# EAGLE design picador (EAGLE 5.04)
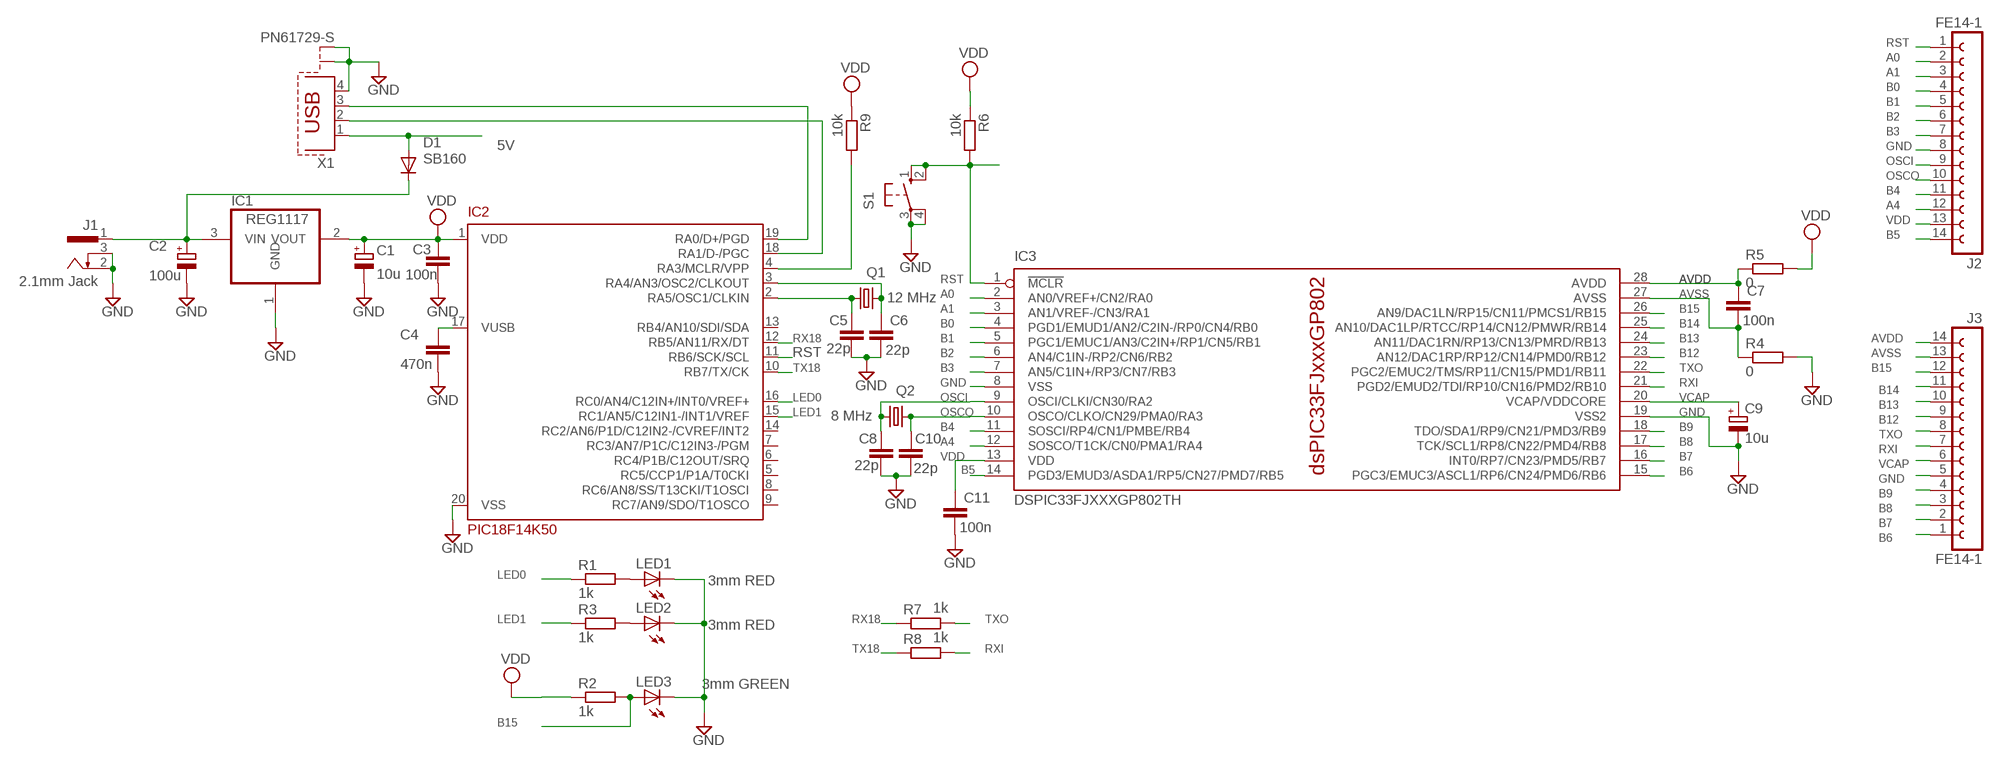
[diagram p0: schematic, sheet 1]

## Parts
C1  10u  CPOL-EUE2-4  [E2-4]
C2  100u  CPOL-EUE2-4  [E2-4]
C3  100n  C-EU025-024X044  [C025-024X044]
C4  470n  C-EU025-024X044  [C025-024X044]
C5  22p  C-EU025-024X044  [C025-024X044]
C6  22p  C-EU025-024X044  [C025-024X044]
C7  100n  C-EU025-024X044  [C025-024X044]
C8  22p  C-EU025-024X044  [C025-024X044]
C9  10u  CPOL-EUE2-4  [E2-4]
C10  22p  C-EU025-024X044  [C025-024X044]
C11  100n  C-EU025-024X044  [C025-024X044]
D1  SB160  SB120  [DO41-10]
IC1  REG1117  [SOT223]
IC2  PIC18F14K50  [DIL20]
IC3  DSPIC33FJXXXGP802TH  [DIL28-3]
J1  2.1mm Jack  733980-62  [733980-62]
J2  FE14-1  [FE13]
J3  FE14-1  [FE13]
LED1  3mm RED  LED3MM  [LED3MM]
LED2  3mm RED  LED3MM  [LED3MM]
LED3  3mm GREEN  LED3MM  [LED3MM]
Q1  12 MHz  CRYSTALHC49U-V  [HC49U-V]
Q2  8 MHz  CRYSTALHC49U-V  [HC49U-V]
R1  1k  R-EU_0204/5  [0204/5]
R2  1k  R-EU_0204/7  [0204/7]
R3  1k  R-EU_0204/5  [0204/5]
R4  0  R-EU_0204/5  [0204/5]
R5  0  R-EU_0204/5  [0204/5]
R6  10k  R-EU_0204/7  [0204/7]
R7  1k  R-EU_0204/7  [0204/7]
R8  1k  R-EU_0204/7  [0204/7]
R9  10k  R-EU_0204/7  [0204/7]
S1  10-XX  [B3F-10XX]
X1  PN61729-S  [PN61729-S]

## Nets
5V [VDD]: D1.A X1.1
A0: IC3.2(AN0/VREF+/CN2/RA0) J2.2
A1: IC3.3(AN1/VREF-/CN3/RA1) J2.3
A4: IC3.12(SOSCO/T1CK/CN0/PMA1/RA4) J2.12
AVDD: C7.1 IC3.28(AVDD) J3.14 R5.1
AVSS [GND]: C7.2 IC3.27(AVSS) J3.13 R4.1
B0: IC3.4(PGD1/EMUD1/AN2/C2IN-/RP0/CN4/RB0) J2.4
B1: IC3.5(PGC1/EMUC1/AN3/C2IN+/RP1/CN5/RB1) J2.5
B2: IC3.6(AN4/C1IN-/RP2/CN6/RB2) J2.6
B3 [GND]: IC3.7(AN5/C1IN+/RP3/CN7/RB3) J2.7
B4: IC3.11(SOSCI/RP4/CN1/PMBE/RB4) J2.11
B5: IC3.14(PGD3/EMUD3/ASDA1/RP5/CN27/PMD7/RB5) J2.14
B6: IC3.15(PGC3/EMUC3/ASCL1/RP6/CN24/PMD6/RB6) J3.1
B7: IC3.16(INT0/RP7/CN23/PMD5/RB7) J3.2
B8: IC3.17(TCK/SCL1/RP8/CN22/PMD4/RB8) J3.3
B9: IC3.18(TDO/SDA1/RP9/CN21/PMD3/RB9) J3.4
B12: IC3.23(AN12/DAC1RP/RP12/CN14/PMD0/RB12) J3.9
B13: IC3.24(AN11/DAC1RN/RP13/CN13/PMRD/RB13) J3.10
B14: IC3.25(AN10/DAC1LP/RTCC/RP14/CN12/PMWR/RB14) J3.11
B15: IC3.26(AN9/DAC1LN/RP15/CN11/PMCS1/RB15) J3.12 LED3.A R2.2
GND [GND]: C1.- C2.- C3.2 C4.2 C5.2 C6.2 C8.2 C9.- C10.2 C11.2 IC1.1(GND) IC2.20(VSS) IC3.8(VSS) IC3.19(VSS2) J1.2 J1.3 J2.8 J3.5 LED1.K(C) LED2.K(C) LED3.K(C) R4.2 S1.3(P) S1.4(P1) X1.4 X1.S1 X1.S2
LED0: IC2.16(RC0/AN4/C12IN+/INT0/VREF+) R1.1
LED1: IC2.15(RC1/AN5/C12IN1-/INT1/VREF) R3.1
N$1: IC2.19(RA0/D+/PGD) X1.3
N$2: IC2.18(RA1/D-/PGC) X1.2
N$3: C4.1 IC2.17(VUSB)
N$4: LED1.A R1.2
N$5: IC2.4(RA3/MCLR/VPP) R9.2
N$6: C2.+ D1.C IC1.3(VIN) J1.1
N$7: LED2.A R3.2
N$9: C5.1 IC2.2(RA5/OSC1/CLKIN) Q1.1
N$10: C6.1 IC2.3(RA4/AN3/OSC2/CLKOUT) Q1.2
OSCI: C8.1 IC3.9(OSCI/CLKI/CN30/RA2) J2.9 Q2.1
OSCO: C10.1 IC3.10(OSCO/CLKO/CN29/PMA0/RA3) J2.10 Q2.2
RST: IC2.11(RB6/SCK/SCL) IC3.1(!MCLR) J2.1 R6.2 S1.1(S) S1.2(S1)
RX18: IC2.12(RB5/AN11/RX/DT) R7.1
RXI: IC3.21(PGD2/EMUD2/TDI/RP10/CN16/PMD2/RB10) J3.7 R8.2
TX18: IC2.10(RB7/TX/CK) R8.1
TXO: IC3.22(PGC2/EMUC2/TMS/RP11/CN15/PMD1/RB11) J3.8 R7.2
VCAP: C9.+ IC3.20(VCAP/VDDCORE) J3.6
VDD: C1.+ C3.1 C11.1 IC1.2(VOUT) IC2.1(VDD) IC3.13(VDD) J2.13 R2.1 R5.2 R6.1 R9.1
Unconnected: IC2.5(RC5/CCP1/P1A/T0CKI) IC2.6(RC4/P1B/C12OUT/SRQ) IC2.7(RC3/AN7/P1C/C12IN3-/PGM) IC2.8(RC6/AN8/SS/T13CKI/T1OSCI) IC2.9(RC7/AN9/SDO/T1OSCO) IC2.13(RB4/AN10/SDI/SDA) IC2.14(RC2/AN6/P1D/C12IN2-/CVREF/INT2)

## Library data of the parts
C1 C2 C9 = resistor:CPOL-EU: POLARIZED CAPACITOR, European symbol
C3-C8 C10 C11 = resistor:C-EU: CAPACITOR, European symbol
D1 = diode:SB120: DIODE
IC1 = burr-brown:REG1117: 800mA and 1A Low Dropout (LDO) Positive Regulator 1.8V, 2.5V, 2.85V, 3.3V, 5V, and Adj
IC2 = microchip-5:PIC18F14K50: Microchip PIC18F14K50 20-Pin USB Flash Microcontroller with nanoWatt XLP Technology; IC: PIC18F14K50-I/P
IC3 = microchip-dspic33:DSPIC33FJXXXGP802: High-Performance, 16-bit Digital Signal Controllers - dsPIC33FJ64GP802 & dsPIC33FJ128GP802 Source: http://ww1.microchip.com/downloads/en/DeviceDoc/70292B.pdf Operating Range: . Up to 40 MIPS operation (at 3.0-3.6V): - Industrial temperature range (-40°C to +85°C) - Extended temperature range (-40°C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
J1 = con-conrad:73398?: FEMALE PRINT CONNECTOR Niedervolt-Steckverbinder Distributor Conrad
J2 J3 = con-lsta:FE14-1: Female 14 pin SIP header
LED1-LED3 = led:LED: LED
Q1 Q2 = crystal:CRYSTAL: CRYSTAL
R1-R9 = resistor:R-EU_: RESISTOR, European symbol
S1 = switch-omron:10-XX: OMRON SWITCH
X1 = con-berg:PN61729-S: BERG USB connector

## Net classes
0 default: width 0.406 mm
1 GND: width 0.762 mm
2 VDD: width 0.762 mm

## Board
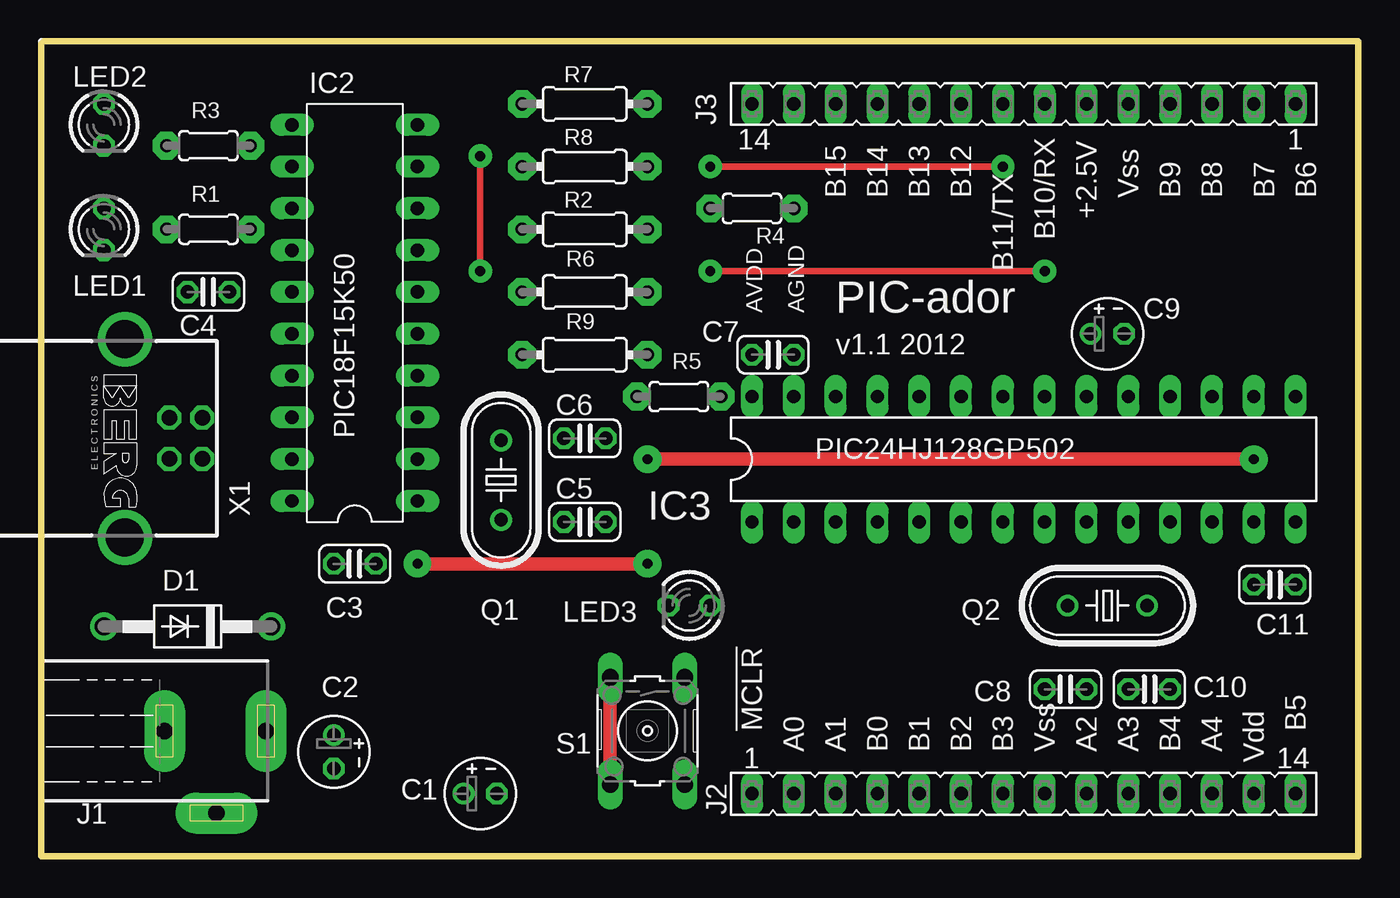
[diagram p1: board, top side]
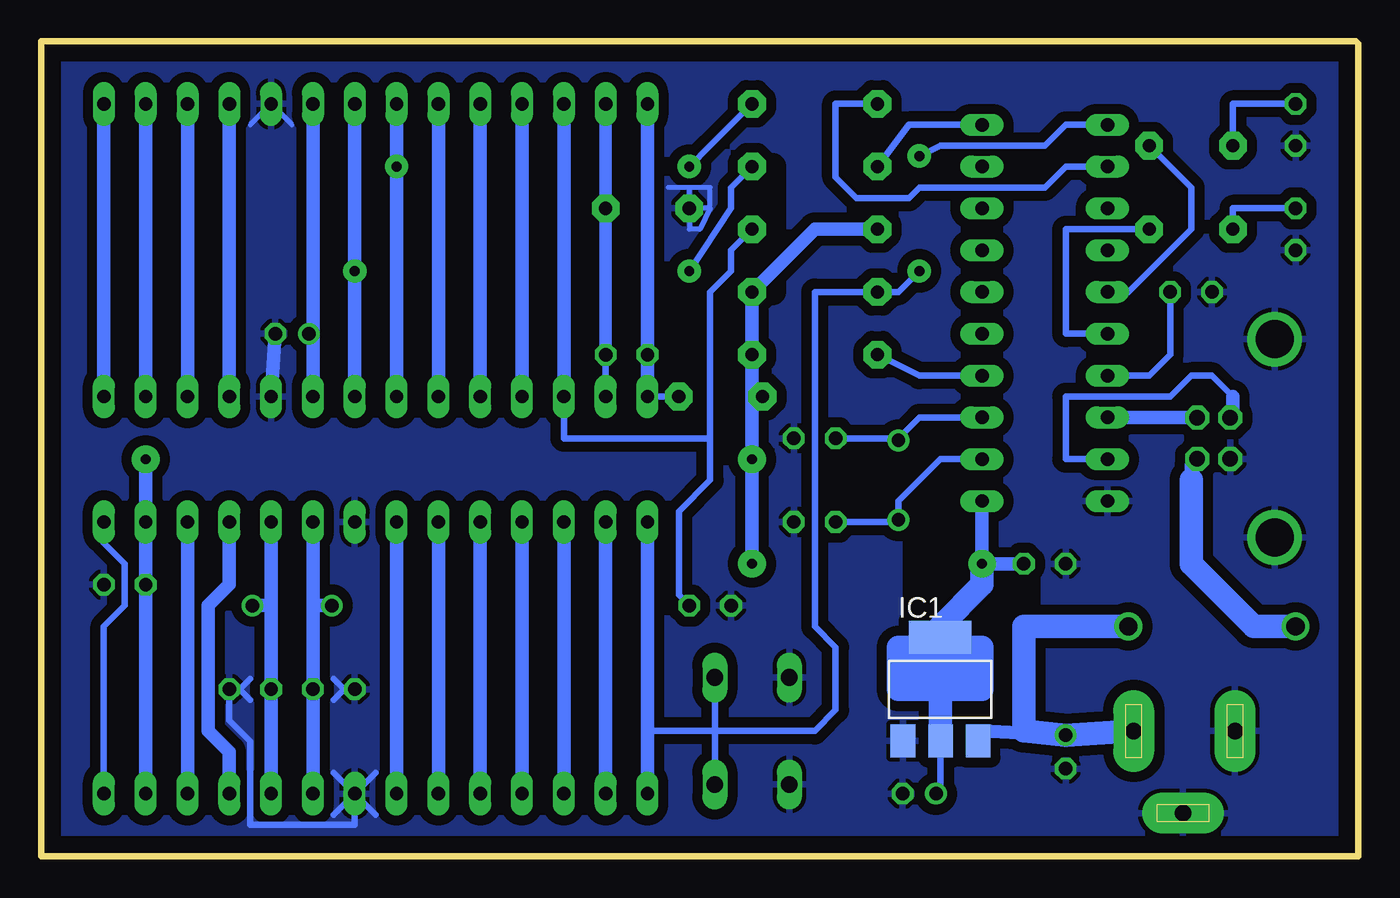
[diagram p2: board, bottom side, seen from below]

Size 80.01 x 49.53 mm. Coordinates in mm from the lower left corner, seen from the top.
Outline: 0,0 79.68,0
Outline: 0,49.52 0,0
Outline: 0.25,49.53 79.68,49.53
Outline: 80.01,0.25 80.01,0 79.76,0
Outline: 0.25,49.53 0,49.53 0,0
Outline: 0,0 79.76,0
Outline: 79.76,0 arc90 80.01,0.25
Outline: 80.01,0.25 80.01,49.53 0.25,49.53
Outline: 0.25,49.53 arc90 0,49.28 0,0
Copper layers (1*16): Top 0.035mm / dielectric 1.5mm / Bottom 0.035mm
Design rules "default *": minimum track width 12mil, minimum drill 24mil, track to track 8mil, track to pad 8mil, pad to pad 8mil, via to via 8mil, smd to smd 8mil, copper to edge 40mil, drill to drill 8mil, minimum pad ring 10mil, minimum via ring 8mil, stop-mask expansion 4mil, vias tented up to drill 0mil, thermal gap 10mil
bRestrict: 5 lines

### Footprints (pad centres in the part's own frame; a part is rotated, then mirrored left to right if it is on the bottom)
E2-4 = drill 0.813 pad 1.27 round: + -1.016,0 | drill 0.813 pad 1.27 octagon: - 1.016,0
C025-024X044 = drill 0.813 octagon: 1 -1.27,0; 2 1.27,0
DO41-10 = drill 1.118 round: A 5.08,0; C -5.08,0
SOT223 = smd 1.499 x 2.007: 1 -2.261,-3.15; 2 0.025,-3.15; 3 2.311,-3.15 | smd 3.81 x 2.007: 4 0,3.15
DIL20 = drill 0.813 long: 1 -11.43,-3.81; 2 -8.89,-3.81; 3 -6.35,-3.81; 4 -3.81,-3.81; 5 -1.27,-3.81; 6 1.27,-3.81; 7 3.81,-3.81; 8 6.35,-3.81; 9 8.89,-3.81; 10 11.43,-3.81; 11 11.43,3.81; 12 8.89,3.81; 13 6.35,3.81; 14 3.81,3.81; 15 1.27,3.81; 16 -1.27,3.81; 17 -3.81,3.81; 18 -6.35,3.81; 19 -8.89,3.81; 20 -11.43,3.81
DIL28-3 = drill 0.813 long: 1 -16.51,-3.81; 2 -13.97,-3.81; 3 -11.43,-3.81; 4 -8.89,-3.81; 5 -6.35,-3.81; 6 -3.81,-3.81; 7 -1.27,-3.81; 8 1.27,-3.81; 9 3.81,-3.81; 10 6.35,-3.81; 11 8.89,-3.81; 12 11.43,-3.81; 13 13.97,-3.81; 14 16.51,-3.81; 15 16.51,3.81; 16 13.97,3.81; 17 11.43,3.81; 18 8.89,3.81; 19 6.35,3.81; 20 3.81,3.81; 21 1.27,3.81; 22 -1.27,3.81; 23 -3.81,3.81; 24 -6.35,3.81; 25 -8.89,3.81; 26 -11.43,3.81; 27 -13.97,3.81; 28 -16.51,3.81
733980-62 = drill 1 pad 2.5 long: 1 0,8.57; 2 0,2.42; 3 5,5.57
FE13 = drill 0.813 long: 1 -15.24,0; 2 -12.7,0; 3 -10.16,0; 4 -7.62,0; 5 -5.08,0; 6 -2.54,0; 7 0,0; 8 2.54,0; 9 5.08,0; 10 7.62,0; 11 10.16,0; 12 12.7,0; 13 15.24,0; 14 17.78,0
LED3MM = drill 0.813 octagon: A -1.27,0; K 1.27,0
HC49U-V = drill 0.813 round: 1 -2.413,0; 2 2.413,0
0204/5 = drill 0.8 pad 1.676 octagon: 1 -2.54,0; 2 2.54,0
0204/7 = drill 0.8 pad 1.676 octagon: 1 -3.81,0; 2 3.81,0
B3F-10XX = drill 1.016 long: 1 -3.251,2.261; 2 3.251,2.261; 3 -3.251,-2.261; 4 3.251,-2.261
PN61729-S = drill 0.95 octagon: 1 1.25,4.71; 2 -1.25,4.71; 3 -1.25,2.71; 4 1.25,2.71 | drill 2.3 pad 2.9 round: S1 -6.02,0; S2 6.02,0

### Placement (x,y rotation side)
C1  26.67,3.81 0 top
C2  17.78,6.35 270 top
C3  19.05,17.78 180 top
C4  10.16,34.29 180 top
C5  33.02,20.32 0 top
C6  33.02,25.4 0 top
C7  44.45,30.48 0 top
C8  62.23,10.16 180 top
C9  64.77,31.75 0 top
C10  67.31,10.16 0 top
C11  74.93,16.51 0.1 top
D1  8.89,13.97 180 top
IC1  25.4,10.16 0 bottom
IC2  19.05,33.02 90 top
IC3  59.69,24.13 0 top
J1  5.08,7.62 270 top
J2  58.42,3.81 0 top
J3  60.96,45.72 180 top
LED1  3.81,38.1 270 top
LED2  3.81,44.45 270 top
LED3  39.37,15.24 180 top
Q1  27.94,22.86 90 top
Q2  64.77,15.24 0 top
R1  10.16,38.1 180 top
R2  33.02,38.1 0 top
R3  10.16,43.18 180 top
R4  43.18,39.37 180 top
R5  38.73,27.94 180 top
R6  33.02,34.29 180 top
R7  33.02,45.72 0 top
R8  33.02,41.91 0 top
R9  33.02,30.48 180 top
S1  36.83,7.62 270 top
X1  5.08,25.4 270 top

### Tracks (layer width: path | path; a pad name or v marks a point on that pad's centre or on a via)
5V
  Bottom 0.813: 10.16,22.86 10.16,23.78 X1.1
  Bottom 1.422: D1.A 6.35,13.97 10.16,17.78 10.16,22.86
A0
  Bottom 0.813: J2.2 IC3.2
A1
  Bottom 0.813: J2.3 IC3.3
A4
  Bottom 0.813: J2.12 IC3.12
AVDD
  Bottom 0.406: C7.1 IC3.28 R5.1 | J3.14 43.18,44.45
  Bottom 0.813: IC3.28 C7.1 J3.14
AVSS
  Bottom 0.406: IC3.27 C7.2
  Bottom 0.762: C7.2 R4.1 45.72,44.45 J3.13
B0
  Bottom 0.813: J2.4 IC3.4
B1
  Bottom 0.813: J2.5 IC3.5
B2
  Bottom 0.813: J2.6 IC3.6
B3
  Bottom 0.813: J2.7 IC3.7
B4
  Bottom 0.813: IC3.11 68.58,16.51 69.85,15.24 69.85,7.62 68.58,6.35 J2.11
B5
  Bottom 0.406: J2.14 76.2,5.08 76.2,13.97 74.93,15.24 74.93,17.78 76.2,19.05 IC3.14
B6
  Bottom 0.813: IC3.15 J3.1
B7
  Bottom 0.813: IC3.16 J3.2
B8
  Bottom 0.813: IC3.17 J3.3
B9
  Bottom 0.813: IC3.18 J3.4
B12
  Bottom 0.813: IC3.23 J3.9
B13
  Bottom 0.813: IC3.24 J3.10
B14
  Bottom 0.813: IC3.25 J3.11
B15
  Bottom 0.406: IC3.26 48.26,26.67 | IC3.26 48.26,29.21 | 39.37,25.4 39.37,22.86 41.27,20.95 41.27,15.88 LED3.A | IC3.26 48.26,29.21 | 39.37,25.4 40.64,25.4 41.91,25.4 46.99,25.4 48.26,25.4 IC3.26 | IC3.26 48.26,29.21 | R2.2 38.1,36.83 38.1,35.56 39.37,34.29 39.37,25.4 | J3.12 48.26,44.45 J3.12
  Bottom 0.813: 48.26,29.21 J3.12
GND
  Top 0.813: S1.4 S1.3
  Bottom 0.305: 39.37,39.37 R4.2 | 39.37,39.37 39.37,40.64 40.64,40.64 | 40.64,40.64 41.91,40.64 | R4.2 40.64,40.64 | R4.2 40.64,38.1 40.01,38.1 39.37,39.37 | 64.77,44.45 J3.5 67.31,44.45
  Bottom 0.406: J2.8 60.96,1.91 67.31,1.91 67.31,6.99 68.58,8.26 C10.2 67.94,10.16 | 59.69,2.54 J2.8 | J2.8 62.23,2.54 | J2.8 62.23,5.08 | J2.8 59.69,5.08 | 67.94,10.16 67.31,9.53 | 67.94,10.16 67.31,10.79 | 61.59,10.16 62.23,10.79 | 61.59,10.16 C8.2 | 62.23,9.53 61.59,10.16
  Bottom 0.813: C9.- IC3.19
  pour Bottom (isolate 0.61): 0,0 80.01,0 80.01,49.53 0,49.53
LED0
  Bottom 0.406: IC2.16 17.78,31.75 17.78,38.1 R1.1
LED1
  Bottom 0.406: IC2.15 13.97,34.29 10.16,38.1 10.16,40.64 R3.1
N$1
  Bottom 0.406: IC2.19 17.78,24.13 17.78,27.94 11.43,27.94 10.16,29.21 8.89,29.21 7.62,27.94
  Bottom 0.813: 7.62,27.94 7.62,26.67 7.79,26.67 X1.3
N$2
  Bottom 0.813: X1.2 15.22,26.65 IC2.18
N$3
  Bottom 0.406: C4.1 11.43,30.48 12.7,29.21 IC2.17
N$4
  Bottom 0.406: LED1.A 7.62,39.37 R1.2
N$5
  Bottom 0.406: R9.2 26.67,29.21 24.13,29.21 IC2.4
N$6
  Bottom 0.406: 22.86,7.62 IC1.3
  Bottom 0.813: C2.+ 22.86,7.62
  Bottom 1.422: J1.1 C2.+ 20.32,7.62 20.32,13.97 D1.C
N$7
  Bottom 0.406: LED2.A 7.62,45.72 R3.2
N$9
  Bottom 0.406: C5.1 27.94,20.32 Q1.1 27.94,21.59 25.4,24.13 IC2.2
N$10
  Bottom 0.406: 27.94,25.4 Q1.2 | 27.94,25.4 C6.1 | 27.94,25.4 Q1.2 | IC2.3 26.67,26.67 27.94,25.4 | 27.94,25.4 Q1.2
N$11
  Bottom 1.422: 22.86,11.43 27.94,11.43 22.86,12.7 | 22.86,12.7 27.94,12.7 27.94,10.16 22.86,10.16 22.86,11.43 | 22.86,11.43 22.86,12.7
OSCI
  Bottom 0.813: J2.9 63.5,11.43 | 63.5,11.43 63.5,15.24 | 63.5,15.24 IC3.9 | 63.5,11.43 C8.1 | 63.5,15.24 Q2.1
OSCO
  Bottom 0.813: J2.10 66.04,11.43 | 66.04,11.43 66.04,15.24 | 66.04,15.24 IC3.10 | 66.04,15.24 Q2.2 | 66.04,11.43 C10.1
RST  (via drill 0.6 pad 1.42)
  Top 0.406: v26.67,35.56 v26.67,42.55
  Bottom 0.406: J2.1 43.18,7.62 39.37,7.62 | 39.37,7.62 39.09,7.62 S1.1 S1.2 | 39.37,7.62 33.02,7.62 31.75,8.89 31.75,12.7 33.02,13.97 33.02,34.29 R6.2 27.94,34.29 v26.67,35.56 | IC2.11 17.78,44.45 19.05,43.18 25.4,43.18 v26.67,42.55
  Bottom 0.813: J2.1 IC3.1
RX18
  Bottom 0.406: IC2.12 17.78,41.91 19.05,40.64 26.67,40.64 27.3,40.01 30.48,40.01 31.75,41.27 31.75,45.72 R7.1
RXI  (via drill 0.6 pad 1.42)
  Top 0.406: v40.64,35.56 v60.96,35.56
  Bottom 0.406: J3.7 60.96,44.45 | R8.2 38.1,40.64 38.1,39.37 v40.64,35.56
  Bottom 0.813: IC3.21 v60.96,35.56 J3.7
TX18
  Bottom 0.406: IC2.10 27.3,44.45 R8.1
TXO  (via drill 0.6 pad 1.42)
  Top 0.406: v40.64,41.91 v58.42,41.91
  Bottom 0.406: J3.8 58.42,44.45 J3.8 | R7.2 39.37,43.18 v40.64,41.91 | v58.42,41.91 J3.8
  Bottom 0.813: IC3.22 v58.42,41.91 J3.8
VCAP
  Bottom 0.406: 63.5,31.75 C9.+
  Bottom 0.813: IC3.20 63.5,31.75 J3.6
VDD  (via drill 0.6 pad 1.68)
  Top 0.813: v36.83,24.13 v73.66,24.13 | v22.86,17.78 v36.83,17.78
  Bottom 0.406: IC1.2 25.4,6.35 25.4,3.81 C1.+ | 36.83,26.67 36.83,27.94 R5.2 | R9.1 R6.1
  Bottom 0.813: J2.13 C11.1 IC3.13 v73.66,24.13 | 36.83,27.94 36.83,26.67 v36.83,24.13 v36.83,17.78 | 36.83,27.94 R5.2 | C3.1 v22.86,17.78 IC2.1 | 36.83,27.94 R9.1 | R9.1 R6.1 | R9.1 R6.1 | 36.83,27.94 R9.1 | R2.1 33.02,38.1 R6.1 | R9.1 R6.1 | R9.1 R6.1
  Bottom 1.422: IC1.2 25.4,7.04 25.4,12.7 25.4,13.97 22.86,16.51 v22.86,17.78

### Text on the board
tNames: B15 | B14 | B13 | B12 | Vss | B9 | B8 | B7 | B6 | +2.5V | B10/RX | B11/TX | AVDD | AGND | PIC-ador | v1.1 2012 | PIC18F15K50 | PIC24HJ128GP502 | !MCLR | B5 | A0 | A1 | B0 | B1 | B2 | B3 | Vss | A2 | A3 | B4 | A4 | Vdd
